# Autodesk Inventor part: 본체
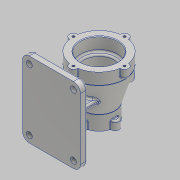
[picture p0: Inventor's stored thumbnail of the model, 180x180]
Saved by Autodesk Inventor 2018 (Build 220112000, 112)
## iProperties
Created: 2020-12
Part Number: 본체
Material: 알루미늄 6061
Document SubType Name: Modeling
Designer: home
Density: 2.7 g/cm^3
Appearance: 알루미늄 - 평지
Mass: 1030.22 g
Surface Area: 851.044 cm^2
Volume: 381.563 cm^3
Author: home
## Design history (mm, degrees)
sketch "스케치1"
  geometry: L1 (50, 65)-(-50, 65); L2 (-50, 65)-(-50, -65); L3 (-50, -65)-(50, -65); L4 (50, -65)-(50, 65); 3 further points
  constraints: 8 end point, 2 midpoint, 2 parallel, 1 horizontal, 1 horizontal alignment, 1 perpendicular, 1 vertical alignment
  dimensions: "d0" = 100 distance of L3.end L2.end; "d1" = 130 distance of L2.end L1.end
extrude "돌출1" new body sketch "스케치1" distance "d2" = 12; taper "d3" = 0 deg
sketch "스케치2"
  geometry: L1 (0, 0)-(82, 0); L2 (82, 56.777)-(82, -59.066); L3 (82, 50)-(126, 50); L4 (126, 50)-(126, 30); L5 (126, 30)-(109.5, -25); L6 (109.5, -25)-(109.5, -50); L7 (109.5, -50)-(82, -50); L8 (114, 50)-(114, 30); L9 (111, 27)-(111, 27); L10 (108, 24)-(108, -17); L11 (105, -20)-(105, -20); L12 (102, -23)-(102, -50); A1 r 3 centre (111, 30) between (111, 27) and (114, 30); A2 r 3 centre (111, 24) between (111, 27) and (108, 24); A3 r 3 centre (105, -17) between (105, -20) and (108, -17); A4 r 3 centre (105, -23) between (105, -20) and (102, -23)
  constraints: 24 end point, 8 point on circle, 8 tangent, 6 perpendicular, 4 centre point, 4 point on line, 3 equal radius, 2 horizontal, 2 vertical, 1 parallel
  dimensions: "d4" = 82 distance of L1.start L1.end; "d5" = 82 distance from line of L1.start L2; "d6" = 56.77681 distance from line of L2.start L1; "d7" = 59.06621 distance from line of L2.end L1; "d8" = 50 distance between parallel lines of L1 L3; "d9" = 50 distance between parallel lines of L1 L7; "d10" = 20 distance of L4.end L3.end; "d11" = 88 diameter of L4 L2; "d12" = 55 diameter of L6 L2; "d13" = 25 distance of L5.end L6.end; "d14" = 64 diameter of L8 L2; "d15" = 52 diameter of L10 L2; "d16" = 40 diameter of L12 L2; "d17" = 23 distance between parallel lines of L3 L9; "d18" = 47 distance between parallel lines of L9 L11; "d19" = 3 radius of A1
revolve "회전1" sketch "스케치2" stored, may be unused: angle "d20" = 90 deg
sketch "스케치3"
  geometry: L1 (-50, 65)-(-50, -65) reference; L2 (50, -65)-(50, 65) reference; L3 (-50, -65)-(50, -65) reference; L4 (-4, -24)-(4, -24); L5 (-4, 24)-(4, 24); L6 (-25, -4)-(-25, 4); L7 (25, -4)-(25, 4); L8 (-25, 4)-(-4, 4); L9 (4, 4)-(25, 4); L10 (-25, -4)-(-4, -4); L11 (4, -4)-(25, -4); L12 (-4, -24)-(-4, -4); L13 (-4, 4)-(-4, 24); L14 (4, -24)-(4, -4); L15 (4, 4)-(4, 24); 1 further point
  constraints: 24 end point, 4 horizontal, 4 parallel, 4 vertical
  dimensions: "d35" = 75 distance between parallel lines of L1 L7; "d36" = 54 distance between parallel lines of L1 L15; "d37" = 54 distance between parallel lines of L1 L14; "d38" = 46 distance between parallel lines of L1 L13; "d39" = 46 distance between parallel lines of L1 L12; "d40" = 69 distance between parallel lines of L3 L8; "d41" = 61 distance between parallel lines of L3 L10; "d42" = 25 distance between parallel lines of L1 L6; "d43" = 69 distance between parallel lines of L9 L3; "d44" = 61 distance between parallel lines of L11 L3; "d45" = 89 distance between parallel lines of L5 L3; "d46" = 41 distance between parallel lines of L4 L3
extrude "돌출2" join sketch "스케치3" stored distance "d47" = 12; taper "d48" = 0 deg
node "작업 평면3"
  node "작업 평면2"
sketch "스케치4"
  geometry: C1 r 17 at (0, -40); 1 further point
  constraints: 1 centre point, 1 coincident
  dimensions: "d51" = 34 diameter of C1
extrude "돌출3" join sketch "스케치4" stored distance "d52" = 12; taper "d53" = 0 deg
hole "구멍1" diameter "d56" = 22; stored, may be unused: countersink angle "d60" = 90 deg, drill point angle "d62" = 0 deg; dims "d54" = 10, "d55" = 10, "d57" = 6, "d58" = 28, "d59" = 1, "d61" = 30
sketch "스케치6"
  geometry: L1 (11, 44)-(-11, 44) reference; C1 r 7 at (0, 44); C2 r 7 at (-44, 0); C3 r 7 at (0, -44); C4 r 7 at (44, 0); A1 r 44 centre (0, 0) between (0, 44) and (-44, 0) reference; 3 further points
  constraints: 4 centre point, 4 coincident, 3 point on circle, 1 midpoint
  dimensions: "d63" = 7 radius of C1; "d64" = 7 radius of C2; "d65" = 7 radius of C3; "d66" = 7 radius of C4; "d67" = 44 distance from line of point (44, 0) L1; "d68" = 88 distance from line of point (0, -44) L1; "d69" = 44 distance from line of A1.end L1
extrude "돌출4" join sketch "스케치6" distance "d70" = 15; taper "d71" = 0 deg
hole "구멍2" sketch "스케치6" diameter "d72" = 4.134; stored, may be unused: countersink angle "d76" = 90 deg, drill point angle "d78" = 118 deg; dims "d73" = 9, "d74" = 28, "d75" = 1, "d77" = 11
sketch "스케치7"
  geometry: C1 r 7 at (0, 27.5); C2 r 7 at (-27.5, 0); C3 r 7 at (0, -27.5); C4 r 7 at (27.5, 0); A1 r 27.5 centre (0, 0) between (0, 27.5) and (-27.5, 0) reference; 3 further points
  constraints: 4 centre point, 4 coincident, 4 point on circle
  dimensions: "d79" = 86.48844 distance of point (0, -82) point (27.5, 0); "d80" = 109.5 distance of point (0, -82) A1.start; "d81" = 54.5 distance of point (0, -82) point (0, -27.5); "d82" = 86.48844 distance of point (0, -82) A1.end; "d83" = 7 radius of C1; "d84" = 7 radius of C2; "d85" = 7 radius of C3; "d86" = 7 radius of C4
extrude "돌출5" join sketch "스케치7" distance "d87" = 15; taper "d88" = 0 deg
hole "구멍3" sketch "스케치7" diameter "d89" = 4.134; stored, may be unused: countersink angle "d93" = 90 deg, drill point angle "d95" = 118 deg; dims "d90" = 9, "d91" = 28, "d92" = 1, "d94" = 11
fillet "모깎기1" dims "d96" = 12
sketch "스케치9"
  geometry: C1 r 5 at (-38, -53); C2 r 5 at (38, -53); C3 r 5 at (38, 53); C4 r 5 at (-38, 53); A1 r 12 centre (-38, -53) between (-50, -53) and (-38, -65) reference; A2 r 12 centre (-38, 53) between (-38, 65) and (-50, 53) reference; A3 r 12 centre (38, -53) between (38, -65) and (50, -53) reference; A4 r 12 centre (38, 53) between (50, 53) and (38, 65) reference; 1 further point
  constraints: 4 centre point, 4 coincident
  dimensions: "d97" = 10 diameter of C1; "d98" = 10 diameter of C2; "d99" = 10 diameter of C3; "d100" = 10 diameter of C4
extrude "돌출6" cut sketch "스케치9" distance "d101" = 20; taper "d102" = 0 deg
fillet "모깎기2" dims "d103" = 3
fillet "모깎기3" dims "d104" = 3, "d105" = 1
fillet "모깎기4" dims "d106" = 1
chamfer "모따기1" distance "d107" = 1; stored, may be unused: second distance "d108" = 2, angle "d109" = 45 deg
sketch "스케치10"
  geometry: L1 (50, -53)-(50, 53) reference; 2 further points
  constraints: 1 horizontal alignment, 1 other
  dimensions: "d110" = 10 distance from line of L1 point (40, 0)
feature "엠보싱1" sketch "스케치10" dims "d0" = 100, "d1" = 130, "d4" = 82, "d5" = 82, "d6" = 56.77681, "d7" = 59.06621, "d8" = 50, "d9" = 50, "d10" = 20, "d11" = 88, "d12" = 55, "d13" = 25, "d14" = 64, "d15" = 52, "d16" = 40, "d17" = 23, "d18" = 47, "d19" = 3, "d111" = 0.5, "d112" = 0
node "솔리드1"
node "작업 평면1"
other parameters: "d23" = 4, "d24" = 4, "d25" = 24, "d26" = 24, "d27" = 24, "d28" = 24, "d29" = 4, "d30" = 4, "d31" = 25, "d32" = 25, "d33" = 25, "d34" = 25, "d49" = -44, "d50" = -45
